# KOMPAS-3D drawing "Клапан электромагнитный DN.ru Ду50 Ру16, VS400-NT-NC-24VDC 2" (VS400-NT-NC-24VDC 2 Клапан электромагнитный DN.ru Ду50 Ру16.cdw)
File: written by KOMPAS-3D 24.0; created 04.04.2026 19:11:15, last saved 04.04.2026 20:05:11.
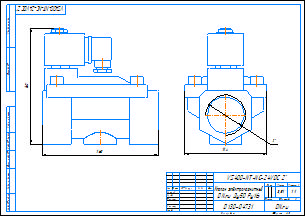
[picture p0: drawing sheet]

Document properties: c3d_UniqueCompID: ef56311e-7521-43dc-8291-0e6108b3d81d; Обозначение: VS400-ET-NC-220VAC 2; Наименование: Клапан электромагнитный DN.ru Ду50 Ру16; Автор: artio; Класс точности: c; Знак неуказанной шероховатости: Шероховатость не задана; Рассекать на разрезах: Да; c3d_UniqueCompID: ef56311e-7521-43dc-8291-0e6108b3d81d; Обозначение: VS400-ET-NC-220VAC 1; Наименование: Клапан электромагнитный DN.ru Ду25 Ру16; Автор: artio; Класс точности: c; Знак неуказанной шероховатости: Шероховатость не задана; Рассекать на разрезах: Да; c3d_UniqueCompID: ef56311e-7521-43dc-8291-0e6108b3d81d; Обозначение: VS400-ET-NC-220VAC 1-2; Наименование: Клапан электромагнитный DN.ru Ду15 Ру16; Автор: artio; Класс точности: c; Знак неуказанной шероховатости: Шероховатость не задана; Рассекать на разрезах: Да; c3d_UniqueCompID: ef56311e-7521-43dc-8291-0e6108b3d81d; Обозначение: VS400-ET-NC-220VAC 3-4; Наименование: Клапан электромагнитный DN.ru Ду20 Ру16; Автор: artio; Класс точности: c; Знак неуказанной шероховатости: Шероховатость не задана; Рассекать на разрезах: Да; c3d_UniqueCompID: ef56311e-7521-43dc-8291-0e6108b3d81d; Обозначение: VS400-ET-NC-220VAC 1 1-4; Наименование: Клапан электромагнитный DN.ru Ду32 Ру16; Автор: artio; Класс точности: c; Знак неуказанной шероховатости: Шероховатость не задана; Рассекать на разрезах: Да; c3d_UniqueCompID: ef56311e-7521-43dc-8291-0e6108b3d81d; Обозначение: VS400-ET-NC-220VAC 3-8; Наименование: Клапан электромагнитный DN.ru Ду10 Ру16; Автор: artio; Класс точности: c; Знак неуказанной шероховатости: Шероховатость не задана; Рассекать на разрезах: Да; c3d_UniqueCompID: ef56311e-7521-43dc-8291-0e6108b3d81d; Обозначение: VS400-ET-NC-220VAC 1 1-2; Наименование: Клапан электромагнитный DN.ru Ду40 Ру16; Автор: artio; Класс точности: c; Знак неуказанной шероховатости: Шероховатость не задана; Рассекать на разрезах: Да; Автор: artio; Форматы листов документа: A3; Полное имя файла: VS400-NT-NC-24VDC 2 Клапан электромагнитный DN.ru Ду50 Ру16.m3d; Масса: 3.509; Наименование: Клапан электромагнитный DN.ru Ду50 Ру16; Количество листов документа: 1; Примечание: D130-04731

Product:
- Body: Тело 1  | qty 1
    Масса: 7.119215
- Part/product: Клапан электромагнитный DN.ru Ду50 Ру16  | designation VS400-NT-NC-24VDC 2
    Масса: 3.509
    Раздел спецификации: Прочие изделия
    Примечание: D130-04731
    additional columns: ef56311e-7521-43dc-8291-0e6108b3d81d; VS400-ET-NC-220VAC 2; artio; c; Шероховатость не задана; Да

Views: Вид 1, Спереди
Referenced files in C:\Users\artio\OneDrive\Рабочий стол\Клапан электромагнитный DN.ru\VS400-ET-NC\VS400-ET-NC-24VDC\: VS400-ET-NC-24VDC 3-8 Клапан электромагнитный DN.ru Ду10 Ру16.m3d
Referenced files in C:\Users\artio\OneDrive\Рабочий стол\Клапан электромагнитный DN.ru\VS400-NT-NC\VS400-NT-NC-24VDC\: VS400-NT-NC-24VDC 2 Клапан электромагнитный DN.ru Ду50 Ру16.m3d
Referenced files in C:\Users\artio\OneDrive\Рабочий стол\Клапан электромагнитный DN.ru\VS400-ET-NC\: VS400-ET-NC-24VDC 3-8 Клапан электромагнитный DN.ru Ду10 Ру16.cdw
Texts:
  VS400-NT-NC-24VDC 2
  Клапан электромагнитный
  DN.ru Ду50 Ру16
  VS400-NT-NC-24VDC 2"
  VS400-NT-NC-24VDC 2"-
  Клапан электромагнитный DN.ru Ду50 Ру16
  VS400-NT-NC-24VDC 2 Клапан электромагнитный DN.ru Ду50 Ру16
Dimensions and other numbers on the sheet: 0; 3; 2; 4; 114; 1:1; 1; 3,51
